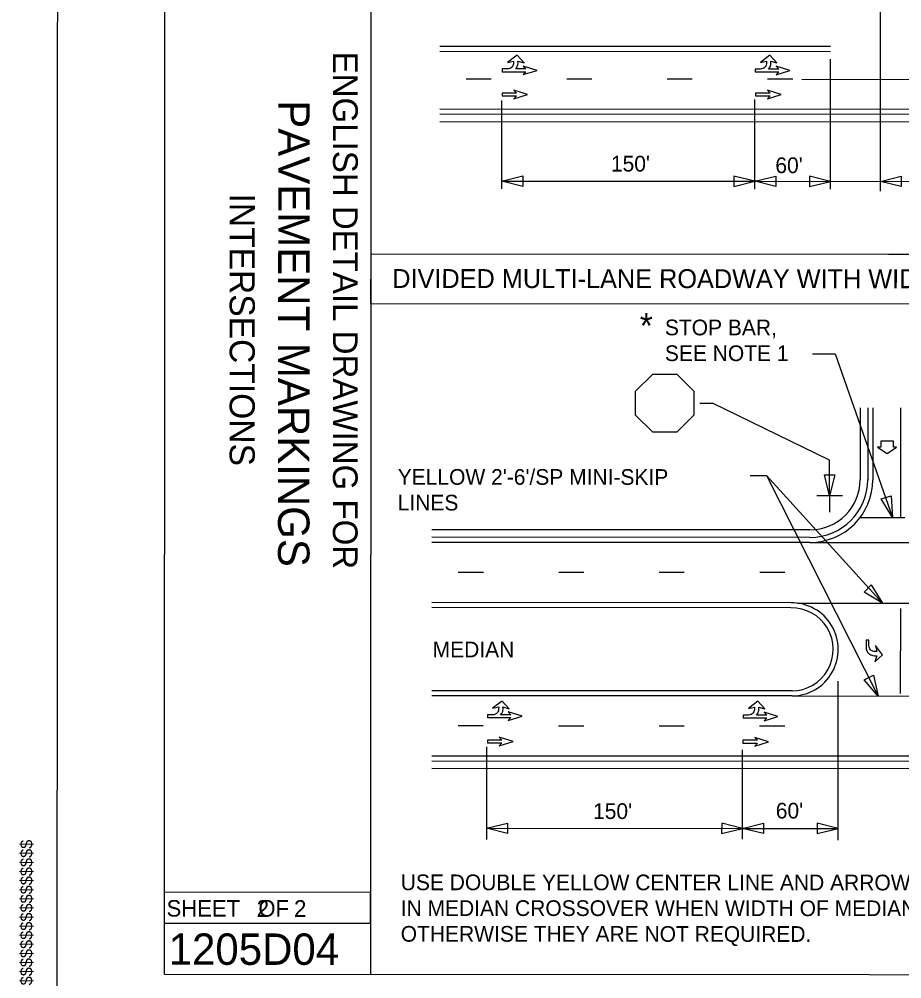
# Model space of a CAD drawing. Extents: x 50667 to 52386, y 46650 to 50479.
# Drawn here: x 50812.7 to 51216.8, y 46904.8 to 47344.1 of the extents above; entities that cross this region are included whole.
import ezdxf

# ---------------------------------------------------------------- set-up
doc = ezdxf.new("R2010")
doc.units = 0
for name, color, linetype in [('Default', 7, 'Continuous'), ('DEV TUBULAR MARKER SECTIONAL VIEW CELL', 7, 'Continuous'), ('Exist Guardrail Text', 7, 'Continuous'), ('Exist Hydro Spring Leader', 7, 'Continuous'), ('Exist Hydro Spring Text', 7, 'Continuous'), ('Exist Right of Way Monument Text', 7, 'Continuous'), ('Gray Area Fill Shapes', 7, 'Continuous'), ('Old_Level_60', 7, 'Continuous'), ('Prop EOT Dash', 7, 'Continuous'), ('Prop SBG', 7, 'Continuous'), ('Sheet North Arrow CELL', 7, 'Continuous'), ('Sheet Sticker Preliminary CELL', 7, 'Continuous')]:
    doc.layers.add(name, color=color, linetype=linetype)

msp = doc.modelspace()

# ---------------------------------------------------------------- linework, layer by layer
at = {"layer": 'Default'}
for p, q in [((51207.05, 47265.47), (51207.09, 47364.89)), ((51184.11, 47331.57), (51005.24, 47331.65)), ((51184.11, 47329.27), (51005.24, 47329.35)), ((51184.08, 47266.36), (51184.11, 47325.87)), ((51149.48, 47266.37), (51149.5, 47307.41)), ((51033.62, 47266.43), (51033.64, 47306.88)), ((51263.44, 47302.78), (51005.23, 47302.9)), ((51263.44, 47300.48), (51005.23, 47300.6)), ((51263.44, 47297.03), (51005.22, 47297.15)), ((51035.79, 47269.97), (51033.62, 47269.97)), ((51033.62, 47269.97), (51149.49, 47269.92)), ((51147.32, 47269.92), (51149.49, 47269.92)), ((51149.49, 47269.92), (51227.55, 47269.88)), ((51151.65, 47269.92), (51149.49, 47269.92)), ((51181.91, 47269.9), (51184.08, 47269.9)), ((52075.41, 47236.01), (50973.63, 47236.53)), ((51175.87, 47190.9), (51186.25, 47190.9)), ((51186.25, 47190.9), (51212.43, 47116.03)), ((51094.92, 47173.9), (51102.73, 47181.7)), ((51102.73, 47181.7), (51113.8, 47181.7)), ((51113.8, 47181.7), (51121.56, 47173.89)), ((51094.91, 47162.83), (51094.92, 47173.9)), ((51121.56, 47173.89), (51121.55, 47162.82)), ((51124.28, 47168.28), (51130.03, 47168.28)), ((51183.72, 47142.31), (51130.03, 47168.28)), ((51102.72, 47155.02), (51094.91, 47162.83)), ((51121.55, 47162.82), (51113.79, 47155.01)), ((51197.74, 47166.2), (51197.72, 47133.29)), ((51201.19, 47166.2), (51201.17, 47133.28)), ((51203.49, 47166.2), (51203.47, 47133.28)), ((51216.14, 47166.2), (51216.12, 47116.03)), ((51113.79, 47155.01), (51102.72, 47155.02)), ((51183.71, 47126), (51183.72, 47142.31)), ((51147.34, 47135.3), (51154.85, 47135.3)), ((51154.85, 47135.3), (51207.86, 47076.79)), ((51154.85, 47135.3), (51205.91, 47034.23)), ((51197.72, 47116.04), (51218.13, 47116.03)), ((51211.82, 47118.15), (51212.45, 47116.07)), ((51174.71, 47110.3), (51001.64, 47110.38)), ((51174.71, 47106.85), (51001.64, 47106.93)), ((51174.71, 47104.55), (51001.64, 47104.63)), ((51165.95, 47074.65), (51001.62, 47074.73)), ((51165.95, 47076.95), (51001.63, 47077.03)), ((51216.1, 47074.28), (51216.08, 47035.38)), ((51187.63, 46968.3), (51187.67, 47041.01)), ((51166.52, 47036.59), (51001.61, 47036.67)), ((51166.52, 47034.29), (51001.61, 47034.37)), ((51026.78, 46968.61), (51026.8, 47011)), ((51143.89, 46968.8), (51143.9, 47009.57)), ((51259.76, 47006.65), (51001.59, 47006.77)), ((51259.76, 47004.35), (51001.59, 47004.47)), ((51259.76, 47000.9), (51001.59, 47001.02)), ((51026.64, 46973.74), (51143.89, 46973.69)), ((51141.72, 46973.69), (51143.89, 46973.69)), ((51143.89, 46973.69), (51187.64, 46973.67)), ((51146.06, 46973.69), (51143.89, 46973.69)), ((51185.47, 46973.67), (51187.64, 46973.67))]:
    msp.add_line(p, q, dxfattribs=at)
for points in [[(51028.81, 47316.69), (51017.31, 47316.7)], [(51074.85, 47316.67), (51063.35, 47316.67)], [(51120.85, 47316.65), (51109.35, 47316.65)], [(51166.85, 47316.63), (51155.35, 47316.63)], [(51025.21, 47090.82), (51013.71, 47090.82)], [(51071.21, 47090.8), (51059.71, 47090.8)], [(51117.21, 47090.77), (51105.71, 47090.78)], [(51163.2, 47090.75), (51151.7, 47090.76)], [(51025.17, 47020.56), (51013.67, 47020.56)], [(51071.17, 47020.53), (51059.67, 47020.54)], [(51117.17, 47020.51), (51105.67, 47020.52)], [(51163.17, 47020.49), (51151.67, 47020.5)]]:
    msp.add_lwpolyline(points, dxfattribs=at)
for centre, radius, start, end in [((51174.74, 47133.34), 28.75, 269.9734, 359.9734), ((51174.74, 47133.34), 26.45, 269.9734, 359.9734), ((51174.74, 47133.34), 23, 269.9734, 359.9734), ((51166.34, 47055.62), 21.33, 270.4866, 91.0489), ((51166.34, 47055.62), 19.03, 270.4866, 91.0489)]:
    msp.add_arc(centre, radius, start, end, dxfattribs=at)
at = {"layer": 'DEV TUBULAR MARKER SECTIONAL VIEW CELL'}
for points in [[(50879.23, 46906.71), (50879.58, 47676.39), (52169.91, 47675.79), (52169.55, 46906.11)], [(50973.62, 47214), (51447.58, 47213.78), (51447.59, 47236.31), (50973.63, 47236.53)]]:
    msp.add_lwpolyline(points, close=True, dxfattribs=at)
at = {"layer": 'Exist Guardrail Text'}
for p, q in [((51189.58, 47126), (51177.94, 47126)), ((51183.71, 47126), (51183.71, 47118.45))]:
    msp.add_line(p, q, dxfattribs=at)
at = {"layer": 'Exist Hydro Spring Leader'}
for p, q in [((51168.97, 47076.79), (51266.17, 47076.78)), ((51166.52, 47034.29), (51268.32, 47034.24))]:
    msp.add_line(p, q, dxfattribs=at)
at = {"layer": 'Exist Hydro Spring Text'}
for p, q in [((51171.06, 47316.61), (51270.68, 47316.57)), ((51174.73, 47104.59), (51259.83, 47104.55))]:
    msp.add_line(p, q, dxfattribs=at)
at = {"layer": 'Exist Right of Way Monument Text'}
msp.add_lwpolyline([(52335.61, 47869.9), (50830.4, 47870.6), (50829.91, 46815.38), (52335.12, 46814.68)], close=True, dxfattribs=at)
at = {"layer": 'Gray Area Fill Shapes'}
msp.add_lwpolyline([(51207.14, 47151.02), (51207.14, 47148.14), (51205.7, 47148.14), (51210.06, 47145.27), (51214.33, 47148.14), (51212.89, 47148.14), (51212.89, 47151.02)], close=True, dxfattribs=at)
at = {"layer": 'Old_Level_60'}
for points in [[(51033.88, 47320.11), (51044.68, 47320.1), (51043.43, 47318.75), (51049.77, 47320.72), (51043.44, 47322.7), (51044.68, 47321.35), (51039.98, 47321.35), (51040.44, 47321.92), (51040.7, 47322.36), (51040.9, 47322.92), (51041, 47323.38), (51041.08, 47323.95), (51041.05, 47324.98), (51043.85, 47324.15), (51040.64, 47327.68), (51036.27, 47324.36), (51039.08, 47324.98), (51039.06, 47324.17), (51039.04, 47323.7), (51038.92, 47323.22), (51038.7, 47322.8), (51038.46, 47322.38), (51038.02, 47321.96), (51037.48, 47321.64), (51036.91, 47321.44), (51036.25, 47321.34), (51033.88, 47321.35)], [(51033.88, 47320.11), (51044.68, 47320.1), (51043.43, 47318.75), (51049.77, 47320.72), (51043.44, 47322.7), (51044.68, 47321.35), (51039.98, 47321.35), (51040.44, 47321.92), (51040.7, 47322.36), (51040.9, 47322.92), (51041, 47323.38), (51041.08, 47323.95), (51041.05, 47324.98), (51043.85, 47324.15), (51040.64, 47327.68), (51036.27, 47324.36), (51039.08, 47324.98), (51039.06, 47324.17), (51039.04, 47323.7), (51038.92, 47323.22), (51038.7, 47322.8), (51038.46, 47322.38), (51038.02, 47321.96), (51037.48, 47321.64), (51036.91, 47321.44), (51036.25, 47321.34), (51033.88, 47321.35)], [(51149.65, 47320.05), (51160.45, 47320.05), (51159.2, 47318.7), (51165.54, 47320.67), (51159.2, 47322.64), (51160.45, 47321.29), (51155.75, 47321.3), (51156.21, 47321.87), (51156.46, 47322.3), (51156.66, 47322.86), (51156.76, 47323.32), (51156.84, 47323.9), (51156.82, 47324.93), (51159.62, 47324.1), (51156.4, 47327.63), (51152.04, 47324.31), (51154.84, 47324.93), (51154.83, 47324.12), (51154.81, 47323.64), (51154.69, 47323.16), (51154.47, 47322.74), (51154.23, 47322.33), (51153.79, 47321.91), (51153.25, 47321.59), (51152.67, 47321.39), (51152.01, 47321.29), (51149.65, 47321.3)], [(51149.65, 47320.05), (51160.45, 47320.05), (51159.2, 47318.7), (51165.54, 47320.67), (51159.2, 47322.64), (51160.45, 47321.29), (51155.75, 47321.3), (51156.21, 47321.87), (51156.46, 47322.3), (51156.66, 47322.86), (51156.76, 47323.32), (51156.84, 47323.9), (51156.82, 47324.93), (51159.62, 47324.1), (51156.4, 47327.63), (51152.04, 47324.31), (51154.84, 47324.93), (51154.83, 47324.12), (51154.81, 47323.64), (51154.69, 47323.16), (51154.47, 47322.74), (51154.23, 47322.33), (51153.79, 47321.91), (51153.25, 47321.59), (51152.67, 47321.39), (51152.01, 47321.29), (51149.65, 47321.3)], [(51027.04, 47024.38), (51037.83, 47024.38), (51036.59, 47023.03), (51042.92, 47025), (51036.59, 47026.97), (51037.83, 47025.62), (51033.13, 47025.63), (51033.59, 47026.2), (51033.85, 47026.64), (51034.05, 47027.19), (51034.15, 47027.65), (51034.23, 47028.23), (51034.2, 47029.26), (51037, 47028.43), (51033.79, 47031.96), (51029.43, 47028.64), (51032.23, 47029.26), (51032.21, 47028.45), (51032.19, 47027.97), (51032.07, 47027.49), (51031.85, 47027.08), (51031.61, 47026.66), (51031.17, 47026.24), (51030.64, 47025.92), (51030.06, 47025.72), (51029.4, 47025.62), (51027.04, 47025.63)], [(51027.04, 47024.38), (51037.83, 47024.38), (51036.59, 47023.03), (51042.92, 47025), (51036.59, 47026.97), (51037.83, 47025.62), (51033.13, 47025.63), (51033.59, 47026.2), (51033.85, 47026.64), (51034.05, 47027.19), (51034.15, 47027.65), (51034.23, 47028.23), (51034.2, 47029.26), (51037, 47028.43), (51033.79, 47031.96), (51029.43, 47028.64), (51032.23, 47029.26), (51032.21, 47028.45), (51032.19, 47027.97), (51032.07, 47027.49), (51031.85, 47027.08), (51031.61, 47026.66), (51031.17, 47026.24), (51030.64, 47025.92), (51030.06, 47025.72), (51029.4, 47025.62), (51027.04, 47025.63)], [(51144.17, 47024.33), (51154.96, 47024.32), (51153.72, 47022.98), (51160.05, 47024.94), (51153.72, 47026.92), (51154.96, 47025.57), (51150.27, 47025.57), (51150.72, 47026.14), (51150.98, 47026.58), (51151.18, 47027.14), (51151.28, 47027.6), (51151.36, 47028.18), (51151.33, 47029.21), (51154.13, 47028.37), (51150.92, 47031.9), (51146.56, 47028.58), (51149.36, 47029.21), (51149.34, 47028.4), (51149.32, 47027.92), (51149.2, 47027.44), (51148.98, 47027.02), (51148.74, 47026.6), (51148.31, 47026.18), (51147.77, 47025.86), (51147.19, 47025.67), (51146.53, 47025.56), (51144.17, 47025.57)], [(51144.17, 47024.33), (51154.96, 47024.32), (51153.72, 47022.98), (51160.05, 47024.94), (51153.72, 47026.92), (51154.96, 47025.57), (51150.27, 47025.57), (51150.72, 47026.14), (51150.98, 47026.58), (51151.18, 47027.14), (51151.28, 47027.6), (51151.36, 47028.18), (51151.33, 47029.21), (51154.13, 47028.37), (51150.92, 47031.9), (51146.56, 47028.58), (51149.36, 47029.21), (51149.34, 47028.4), (51149.32, 47027.92), (51149.2, 47027.44), (51148.98, 47027.02), (51148.74, 47026.6), (51148.31, 47026.18), (51147.77, 47025.86), (51147.19, 47025.67), (51146.53, 47025.56), (51144.17, 47025.57)]]:
    msp.add_lwpolyline(points, close=True, dxfattribs=at)
at = {"layer": 'Prop EOT Dash'}
for points in [[(51043.21, 47267.57), (51033.62, 47269.97), (51043.21, 47272.36)], [(51043.21, 47267.57), (51033.62, 47269.97), (51043.21, 47272.36)], [(51139.9, 47267.52), (51149.49, 47269.92), (51139.9, 47272.32)], [(51139.9, 47267.52), (51149.49, 47269.92), (51139.9, 47272.32)], [(51159.07, 47267.52), (51149.49, 47269.92), (51159.07, 47272.31)], [(51159.07, 47267.52), (51149.49, 47269.92), (51159.07, 47272.31)], [(51174.5, 47267.51), (51184.08, 47269.9), (51174.5, 47272.3)], [(51174.5, 47267.51), (51184.08, 47269.9), (51174.5, 47272.3)], [(51216.54, 47267.51), (51207.05, 47269.89), (51216.54, 47272.26)], [(51216.54, 47267.51), (51207.05, 47269.89), (51216.54, 47272.26)], [(51216.54, 47267.51), (51207.05, 47269.89), (51216.54, 47272.26)], [(51216.54, 47267.51), (51207.05, 47269.89), (51216.54, 47272.26)], [(51186.09, 47135.48), (51183.71, 47126), (51181.35, 47135.49)], [(51186.09, 47135.48), (51183.71, 47126), (51181.35, 47135.49)], [(51211.94, 47125.94), (51212.45, 47116.07), (51207.36, 47124.54)], [(51211.94, 47125.94), (51212.45, 47116.07), (51207.36, 47124.54)], [(51202.8, 47085.16), (51207.86, 47076.79), (51199.46, 47081.79)], [(51202.8, 47085.16), (51207.86, 47076.79), (51199.46, 47081.79)], [(51203.77, 47043.78), (51205.91, 47034.23), (51199.53, 47041.64)], [(51203.77, 47043.78), (51205.91, 47034.23), (51199.53, 47041.64)], [(51036.22, 46971.34), (51026.64, 46973.74), (51036.22, 46976.13)], [(51036.22, 46971.34), (51026.64, 46973.74), (51036.22, 46976.13)], [(51134.3, 46971.29), (51143.89, 46973.69), (51134.31, 46976.09)], [(51134.3, 46971.29), (51143.89, 46973.69), (51134.31, 46976.09)], [(51153.47, 46971.29), (51143.89, 46973.69), (51153.47, 46976.08)], [(51153.47, 46971.29), (51143.89, 46973.69), (51153.47, 46976.08)], [(51178.05, 46971.27), (51187.64, 46973.67), (51178.05, 46976.07)], [(51178.05, 46971.27), (51187.64, 46973.67), (51178.05, 46976.07)]]:
    msp.add_lwpolyline(points, close=True, dxfattribs=at)
at = {"layer": 'Prop SBG'}
for points in [[(51201.66, 47059.83), (51200.41, 47059.83), (51200.41, 47056.61), (51200.44, 47056.02), (51200.52, 47055.57), (51200.68, 47055.07), (51200.89, 47054.66), (51201.11, 47054.35), (51201.46, 47053.94), (51201.77, 47053.66), (51202.15, 47053.37), (51202.64, 47053.07), (51203.03, 47052.92), (51203.56, 47052.76), (51204.28, 47052.66), (51205.29, 47052.66), (51204.45, 47049.86), (51207.99, 47053.08), (51204.67, 47057.44), (51205.29, 47054.64), (51204.46, 47054.64), (51203.99, 47054.66), (51203.56, 47054.78), (51203.23, 47054.94), (51202.8, 47055.19), (51202.5, 47055.43), (51202.17, 47055.84), (51201.93, 47056.31), (51201.76, 47056.78), (51201.66, 47057.44)], [(51201.66, 47059.83), (51200.41, 47059.83), (51200.41, 47056.61), (51200.44, 47056.02), (51200.52, 47055.57), (51200.68, 47055.08), (51200.89, 47054.66), (51201.11, 47054.35), (51201.46, 47053.94), (51201.78, 47053.66), (51202.15, 47053.37), (51202.64, 47053.07), (51203.03, 47052.92), (51203.56, 47052.76), (51204.29, 47052.66), (51205.29, 47052.66), (51204.46, 47049.86), (51207.99, 47053.08), (51204.67, 47057.44), (51205.29, 47054.64), (51204.46, 47054.64), (51203.99, 47054.66), (51203.56, 47054.78), (51203.23, 47054.94), (51202.8, 47055.19), (51202.5, 47055.43), (51202.17, 47055.84), (51201.93, 47056.31), (51201.76, 47056.78), (51201.66, 47057.44)]]:
    msp.add_lwpolyline(points, close=True, dxfattribs=at)
at = {"layer": 'Sheet North Arrow CELL'}
for points in [[(51039.15, 47311.65), (51040.39, 47310.3), (51033.75, 47310.31), (51033.75, 47309.06), (51040.39, 47309.06), (51039.14, 47307.71), (51045.48, 47309.68)], [(51039.15, 47311.65), (51040.39, 47310.3), (51033.75, 47310.31), (51033.75, 47309.06), (51040.39, 47309.06), (51039.14, 47307.71), (51045.48, 47309.68)], [(51155.22, 47311.6), (51156.46, 47310.25), (51149.82, 47310.25), (51149.81, 47309.01), (51156.46, 47309), (51155.21, 47307.66), (51161.55, 47309.62)], [(51155.22, 47311.6), (51156.46, 47310.25), (51149.82, 47310.25), (51149.81, 47309.01), (51156.46, 47309), (51155.21, 47307.66), (51161.55, 47309.62)], [(51032.45, 47015.39), (51033.69, 47014.04), (51027.05, 47014.04), (51027.05, 47012.8), (51033.69, 47012.79), (51032.45, 47011.45), (51038.78, 47013.41)], [(51032.45, 47015.39), (51033.69, 47014.04), (51027.05, 47014.04), (51027.05, 47012.8), (51033.69, 47012.79), (51032.45, 47011.45), (51038.78, 47013.41)], [(51149.42, 47015.34), (51150.67, 47013.99), (51144.02, 47013.99), (51144.02, 47012.74), (51150.67, 47012.74), (51149.42, 47011.39), (51155.75, 47013.36)], [(51149.42, 47015.34), (51150.67, 47013.99), (51144.02, 47013.99), (51144.02, 47012.74), (51150.67, 47012.74), (51149.42, 47011.39), (51155.75, 47013.36)]]:
    msp.add_lwpolyline(points, close=True, dxfattribs=at)
at = {"layer": 'Sheet Sticker Preliminary CELL'}
msp.add_lwpolyline([(50973.73, 47445.44), (50879.43, 47445.48), (50879.54, 47676.39), (50973.83, 47676.34), (50973.48, 46906.67), (50879.18, 46906.71), (50879.19, 46930.29), (50973.49, 46930.24), (50973.5, 46944.38), (50879.2, 46944.42)], dxfattribs=at)

# ---------------------------------------------------------------- texts
at = {"layer": 'Default'}
for s, height, rotation, p in [('PAVEMENT MARKINGS', 14.3748, 269.9734, (50931.31, 47307.03)), ("150'", 7.187, 359.9734, (51083.6, 47274.41)), ("60'", 7.187, 359.9734, (51158.88, 47273.68)), ('INTERSECTIONS', 11.4998, 269.9734, (50909.1, 47264.34)), ('DIVIDED MULTI-LANE ROADWAY WITH WIDE MEDIAN CROSSOVER', 8.652, 359.9734, (50983.51, 47221.09)), ('*', 11.5, 359.9734, (51096.83, 47198.11)), ('STOP BAR, ', 7.187, 359.9734, (51108.31, 47199.42)), ('SEE NOTE 1', 7.187, 359.9734, (51108.3, 47187.63)), ("YELLOW 2'-6'/SP MINI-SKIP ", 7.1874, 359.9734, (50986.02, 47131.01)), ('LINES', 7.187, 359.9734, (50986.01, 47119.23)), ('MEDIAN', 7.187, 359.9734, (51001.99, 47051.99)), ("150'", 7.187, 359.9734, (51075.42, 46977.98)), ("60'", 7.187, 359.9734, (51159.08, 46978.21)), ('USE DOUBLE YELLOW CENTER LINE AND ARROW SYMBOLS', 7.1874, 359.9734, (50987.39, 46945.39)), ('IN MEDIAN CROSSOVER WHEN WIDTH OF MEDIAN EXCEEDS 30 FT,', 7.1874, 359.9734, (50987.38, 46933.6)), ('OTHERWISE THEY ARE NOT REQUIRED.', 7.1874, 359.9734, (50987.38, 46921.81))]:
    msp.add_text(s, height=height, rotation=rotation, dxfattribs=at).set_placement(p)
at = {"layer": 'DEV TUBULAR MARKER SECTIONAL VIEW CELL'}
for s, height, p in [('2    2', 7.667, (50921.41, 46933.14)), ('1205D04', 14.375, (50881.15, 46911.22))]:
    msp.add_text(s, height=height, rotation=359.9734, dxfattribs=at).set_placement(p)
at = {"layer": 'Exist Right of Way Monument Text'}
msp.add_text('$$$$$$$$$$$$$$$$DGN$$$$$$$$$$$$$$$$', height=5.6034, rotation=89.9734, dxfattribs=at).set_placement((50818.75, 46818.48))
at = {"layer": 'Sheet Sticker Preliminary CELL'}
for s, height, rotation, p in [('ENGLISH DETAIL DRAWING FOR', 11.3078, 269.9734, (50956.42, 47329.28)), ('SHEET   OF', 7.542, 359.9734, (50880.2, 46933.31))]:
    msp.add_text(s, height=height, rotation=rotation, dxfattribs=at).set_placement(p)

doc.saveas('drawing.dxf')
